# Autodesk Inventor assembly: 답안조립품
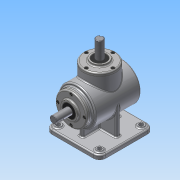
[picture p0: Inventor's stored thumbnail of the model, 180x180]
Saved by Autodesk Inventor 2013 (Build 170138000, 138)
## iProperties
Created: 2015-07
Part Number: 답안조립품
Document SubType Name: Assembly
Designer: Administrator
Author: Administrator
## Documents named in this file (14)
- C:\Users\Administrator\Desktop\450706V1019\답안조립품.iam
- C:\Users\Administrator\Desktop\450706V1019\1-본체.ipt
- C:\Users\Administrator\Desktop\450706V1019\커버.ipt
- C:\Users\Administrator\Desktop\450706V1019\오일실.ipt
- C:\Users\Administrator\Desktop\450706V1019\M4.ipt
- C:\Users\Administrator\Desktop\450706V1019\베어링 6203.ipt
- C:\Users\Administrator\Desktop\450706V1019\메인 축.ipt
- 메인 축.ipt
- C:\Users\Administrator\Desktop\450706V1019\키 5x5.ipt
- C:\Users\Administrator\Desktop\450706V1019\메인 베벨기어.ipt
- C:\Users\Administrator\Desktop\450706V1019\서브 축.ipt
- 서브 축.ipt
- C:\Users\Administrator\Desktop\450706V1019\키 4x4.ipt
- C:\Users\Administrator\Desktop\450706V1019\서브 베벨기어.ipt
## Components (9 placed, 2 different names)
1. 1-본체:1
2. M4:1
3. M4:2
4. M4:3
5. M4:4
6. M4:5
7. M4:6
8. M4:7
9. M4:8
